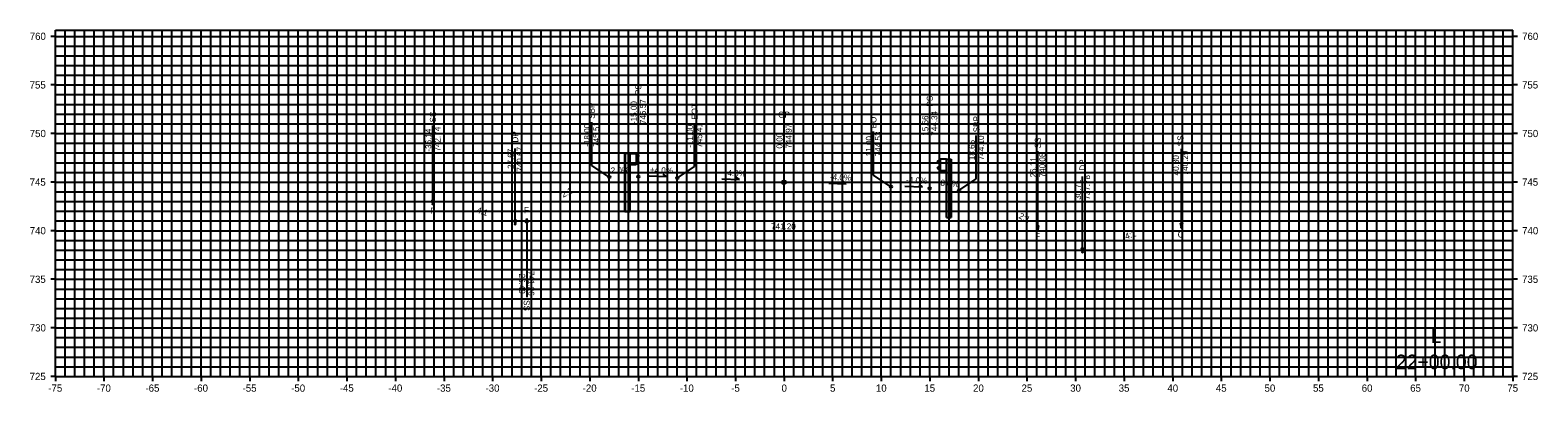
# Model space of a CAD drawing. Extents: x -78 to 78, y 723 to 761.
import ezdxf

# ---------------------------------------------------------------- set-up
doc = ezdxf.new("R2010")
doc.units = 0
for name, color, linetype in [('_CIVIL_CONSTRUCTION', 7, 'Continuous'), ('Default', 7, 'Continuous'), ('E_NCDOT_XS_Center_Line_Elevation_Label', 7, 'Continuous'), ('P_NCDOT_XS_Label_Finished_Grade', 7, 'Continuous'), ('P_NCDOT_XS_Label_Grade_Point', 7, 'Continuous'), ('P_NCDOT_XS_Label_Grading_Side_Slope', 7, 'Continuous'), ('P_NCDOT_XS_Label_Slope_Half_Size', 7, 'Continuous'), ('P_NCDOT_XS_Label_Slope_Superelevation', 7, 'Continuous'), ('P_NCDOT_XS_Leader_Line', 7, 'Continuous'), ('P_NCDOT_XS_Sheet_Alignment_Station_Label', 7, 'Continuous'), ('P_NCDOT_XS_Sheet_Annotation_Label', 7, 'Continuous'), ('P_NCDOT_XS_Sheet_Grid_Border', 7, 'Continuous'), ('P_NCDOT_XS_Slope_Label', 7, 'Continuous'), ('P_RDY_XS_Label_Finished_Grade', 7, 'Continuous'), ('Prop XS Label Slope Superelevation', 7, 'Continuous'), ('Sheet_Grid_Major', 7, 'Continuous'), ('Sheet_Grid_Middle', 7, 'Continuous'), ('Sheet_Grid_Minor', 7, 'Continuous')]:
    doc.layers.add(name, color=color, linetype=linetype)

msp = doc.modelspace()

# ---------------------------------------------------------------- linework, layer by layer
at = {"layer": '_CIVIL_CONSTRUCTION'}
for centre in [(-36.14, 742.74), (-27.67, 740.67), (40.9, 740.32), (30.71, 737.78), (30.71, 737.78)]:
    msp.add_circle(centre, 0.05, dxfattribs=at)
at = {"layer": 'Default'}
for p, q in [((-15.88, 747.95), (-16.38, 747.95)), ((-16.38, 747.95), (-16.36, 747.95)), ((-16.38, 741.95), (-16.38, 747.95)), ((-16.36, 747.95), (-16.36, 741.95)), ((-15.89, 747.95), (-15.88, 747.95)), ((-15.89, 741.95), (-15.89, 747.95)), ((-15.88, 747.95), (-15.21, 747.95)), ((-15.88, 747.95), (-15.88, 741.95)), ((-15.21, 747.95), (-15.21, 746.78)), ((-15.21, 746.78), (-15.88, 746.78)), ((-15.21, 747.87), (-15.12, 747.85)), ((-15.21, 747.41), (-15.21, 747.37)), ((-15.21, 747.37), (-15.21, 747.32)), ((-15.12, 746.88), (-15.21, 746.86)), ((-14.97, 747.62), (-15.18, 747.48)), ((-15.18, 747.25), (-14.97, 747.11)), ((-15.1, 747.85), (-14.97, 747.75)), ((-14.97, 746.98), (-15.1, 746.88)), ((15.94, 747.27), (15.8, 747.17)), ((15.8, 746.4), (15.94, 746.3)), ((15.81, 747.04), (16.01, 746.9)), ((16.01, 746.67), (15.81, 746.53)), ((16.04, 747.29), (15.96, 747.27)), ((16.71, 747.37), (16.05, 747.37)), ((16.05, 747.37), (16.05, 746.2)), ((16.05, 746.83), (16.05, 746.78)), ((16.05, 746.78), (16.05, 746.74)), ((16.71, 747.37), (17.21, 747.37)), ((16.73, 747.37), (16.71, 747.37)), ((16.71, 747.37), (16.71, 741.37)), ((16.73, 741.37), (16.73, 747.37)), ((17.21, 747.37), (17.2, 747.37)), ((17.2, 747.37), (17.2, 741.37)), ((17.21, 741.37), (17.21, 747.37)), ((15.96, 746.3), (16.04, 746.28)), ((16.05, 746.2), (16.71, 746.2)), ((-15.88, 741.95), (-16.38, 741.95)), ((-16.36, 741.95), (-16.38, 741.95)), ((-15.88, 741.95), (-15.89, 741.95)), ((16.71, 741.37), (17.21, 741.37)), ((16.71, 741.37), (16.73, 741.37)), ((17.2, 741.37), (17.21, 741.37))]:
    msp.add_line(p, q, dxfattribs=at)
for centre, radius, start, end in [((-15.13, 747.41), 0.0787, 124.6522, 179.98), ((-15.13, 747.32), 0.0787, 180.02, 235.3478), ((-15.12, 747.82), 0.0328, 54.7024, 80), ((-15.12, 746.91), 0.0328, 280, 305.2976), ((-15.01, 747.69), 0.0787, 304.6522, 54.7024), ((-15.01, 747.05), 0.0787, 305.2976, 55.3478), ((15.85, 747.11), 0.0787, 125.2976, 235.3478), ((15.85, 746.46), 0.0787, 124.6522, 234.7024), ((15.96, 747.24), 0.0328, 100, 125.2976), ((15.97, 746.83), 0.0787, 0.02, 55.3478), ((15.97, 746.74), 0.0787, 304.6522, 359.98), ((15.96, 746.33), 0.0328, 234.7024, 260)]:
    msp.add_arc(centre, radius, start, end, dxfattribs=at)
at = {"layer": 'P_NCDOT_XS_Leader_Line'}
for p, q in [((-15, 745.57), (-15, 753.37)), ((0, 744.97), (0, 751.21)), ((15, 744.37), (15, 752.17)), ((-36.14, 742.74), (-36.14, 750.84)), ((-27.67, 740.67), (-27.67, 748.47)), ((26.11, 740.08), (26.11, 748.18)), ((40.9, 740.32), (40.9, 748.42)), ((30.71, 737.78), (30.71, 745.58)), ((-26.49, 741.26), (-26.49, 733.16))]:
    msp.add_line(p, q, dxfattribs=at)
for points in [[(0.15, 744.82), (-0.15, 744.82), (-0.15, 745.12), (0.15, 745.12)], [(-36.14, 742.74), (-36.23, 743.15), (-36.05, 743.15)], [(-27.67, 740.67), (-27.76, 741.08), (-27.59, 741.08)], [(-26.49, 741.26), (-26.4, 740.85), (-26.58, 740.85)], [(26.11, 740.08), (26.03, 740.49), (26.2, 740.49)], [(40.9, 740.32), (40.81, 740.73), (40.99, 740.73)], [(30.71, 737.78), (30.62, 738.19), (30.8, 738.19)]]:
    msp.add_lwpolyline(points, close=True, dxfattribs=at)
for centre in [(-18, 745.51), (-15, 745.57), (-11, 745.41), (11, 744.53), (15, 744.37), (18, 744.13)]:
    msp.add_circle(centre, 0.12, dxfattribs=at)
at = {"layer": 'P_NCDOT_XS_Sheet_Grid_Border'}
for p, q in [((-75, 760.64), (75, 760.64)), ((-75, 725), (-75, 760.64)), ((75, 725), (75, 760.64)), ((-75, 725), (75, 725))]:
    msp.add_line(p, q, dxfattribs=at)
at = {"layer": 'P_RDY_XS_Label_Finished_Grade'}
for p, q in [((-19.78, 746.7), (-19.78, 751.18)), ((-9.22, 746.6), (-9.22, 751.08)), ((9.22, 745.72), (9.22, 750.2)), ((19.78, 745.32), (19.78, 749.8)), ((-18, 745.51), (-19.78, 746.7)), ((-11, 745.41), (-9.22, 746.6)), ((11, 744.53), (9.22, 745.72)), ((18, 744.13), (19.78, 745.32))]:
    msp.add_line(p, q, dxfattribs=at)
at = {"layer": 'Prop XS Label Slope Superelevation'}
for p, q in [((-13.9, 745.64), (-12.1, 745.57)), ((-12.1, 745.57), (-12.43, 745.82)), ((-6.4, 745.34), (-4.6, 745.27)), ((-4.6, 745.27), (-4.93, 745.52)), ((4.6, 744.9), (6.4, 744.83)), ((6.4, 744.83), (6.07, 745.08)), ((12.43, 744.59), (14.23, 744.52)), ((14.23, 744.52), (13.89, 744.77))]:
    msp.add_line(p, q, dxfattribs=at)
at = {"layer": 'Sheet_Grid_Major'}
for p, q in [((-70, 725), (-70, 760.64)), ((-60, 725), (-60, 760.64)), ((-50, 725), (-50, 760.64)), ((-40, 725), (-40, 760.64)), ((-30, 725), (-30, 760.64)), ((-20, 725), (-20, 760.64)), ((-10, 725), (-10, 760.64)), ((0, 725), (0, 760.64)), ((10, 725), (10, 760.64)), ((20, 725), (20, 760.64)), ((30, 725), (30, 760.64)), ((40, 725), (40, 760.64)), ((50, 725), (50, 760.64)), ((60, 725), (60, 760.64)), ((70, 725), (70, 760.64)), ((-75, 760), (75, 760)), ((-75, 750), (75, 750)), ((-75, 740), (75, 740)), ((-75, 730), (75, 730))]:
    msp.add_line(p, q, dxfattribs=at)
at = {"layer": 'Sheet_Grid_Middle'}
for p, q in [((-70, 725), (-70, 760.64)), ((-65, 725), (-65, 760.64)), ((-60, 725), (-60, 760.64)), ((-55, 725), (-55, 760.64)), ((-50, 725), (-50, 760.64)), ((-45, 725), (-45, 760.64)), ((-40, 725), (-40, 760.64)), ((-35, 725), (-35, 760.64)), ((-30, 725), (-30, 760.64)), ((-25, 725), (-25, 760.64)), ((-20, 725), (-20, 760.64)), ((-15, 725), (-15, 760.64)), ((-10, 725), (-10, 760.64)), ((-5, 725), (-5, 760.64)), ((0, 725), (0, 760.64)), ((5, 725), (5, 760.64)), ((10, 725), (10, 760.64)), ((15, 725), (15, 760.64)), ((20, 725), (20, 760.64)), ((25, 725), (25, 760.64)), ((30, 725), (30, 760.64)), ((35, 725), (35, 760.64)), ((40, 725), (40, 760.64)), ((45, 725), (45, 760.64)), ((50, 725), (50, 760.64)), ((55, 725), (55, 760.64)), ((60, 725), (60, 760.64)), ((65, 725), (65, 760.64)), ((70, 725), (70, 760.64)), ((-75, 760), (-75.48, 760)), ((-75, 760), (75, 760)), ((75.48, 760), (75, 760)), ((-75, 755), (-75.48, 755)), ((-75, 755), (75, 755)), ((75.48, 755), (75, 755)), ((-75, 750), (-75.48, 750)), ((-75, 750), (75, 750)), ((75.48, 750), (75, 750)), ((-75, 745), (-75.48, 745)), ((-75, 745), (75, 745)), ((75.48, 745), (75, 745)), ((-75, 740), (-75.48, 740)), ((-75, 740), (75, 740)), ((75.48, 740), (75, 740)), ((-75, 735), (-75.48, 735)), ((-75, 735), (75, 735)), ((75.48, 735), (75, 735)), ((-75, 730), (-75.48, 730)), ((-75, 730), (75, 730)), ((75.48, 730), (75, 730)), ((-75, 725), (-75.48, 725)), ((-75, 725), (-75, 724.52)), ((-70, 725), (-70, 724.52)), ((-65, 725), (-65, 724.52)), ((-60, 725), (-60, 724.52)), ((-55, 725), (-55, 724.52)), ((-50, 725), (-50, 724.52)), ((-45, 725), (-45, 724.52)), ((-40, 725), (-40, 724.52)), ((-35, 725), (-35, 724.52)), ((-30, 725), (-30, 724.52)), ((-25, 725), (-25, 724.52)), ((-20, 725), (-20, 724.52)), ((-15, 725), (-15, 724.52)), ((-10, 725), (-10, 724.52)), ((-5, 725), (-5, 724.52)), ((0, 725), (0, 724.52)), ((5, 725), (5, 724.52)), ((10, 725), (10, 724.52)), ((15, 725), (15, 724.52)), ((20, 725), (20, 724.52)), ((25, 725), (25, 724.52)), ((30, 725), (30, 724.52)), ((35, 725), (35, 724.52)), ((40, 725), (40, 724.52)), ((45, 725), (45, 724.52)), ((50, 725), (50, 724.52)), ((55, 725), (55, 724.52)), ((60, 725), (60, 724.52)), ((65, 725), (65, 724.52)), ((70, 725), (70, 724.52)), ((75, 725), (75, 724.52)), ((75.48, 725), (75, 725))]:
    msp.add_line(p, q, dxfattribs=at)
at = {"layer": 'Sheet_Grid_Minor'}
for p, q in [((-74, 725), (-74, 760.64)), ((-73, 725), (-73, 760.64)), ((-72, 725), (-72, 760.64)), ((-71, 725), (-71, 760.64)), ((-69, 725), (-69, 760.64)), ((-68, 725), (-68, 760.64)), ((-67, 725), (-67, 760.64)), ((-66, 725), (-66, 760.64)), ((-64, 725), (-64, 760.64)), ((-63, 725), (-63, 760.64)), ((-62, 725), (-62, 760.64)), ((-61, 725), (-61, 760.64)), ((-59, 725), (-59, 760.64)), ((-58, 725), (-58, 760.64)), ((-57, 725), (-57, 760.64)), ((-56, 725), (-56, 760.64)), ((-54, 725), (-54, 760.64)), ((-53, 725), (-53, 760.64)), ((-52, 725), (-52, 760.64)), ((-51, 725), (-51, 760.64)), ((-49, 725), (-49, 760.64)), ((-48, 725), (-48, 760.64)), ((-47, 725), (-47, 760.64)), ((-46, 725), (-46, 760.64)), ((-44, 725), (-44, 760.64)), ((-43, 725), (-43, 760.64)), ((-42, 725), (-42, 760.64)), ((-41, 725), (-41, 760.64)), ((-39, 725), (-39, 760.64)), ((-38, 725), (-38, 760.64)), ((-37, 725), (-37, 760.64)), ((-36, 725), (-36, 760.64)), ((-34, 725), (-34, 760.64)), ((-33, 725), (-33, 760.64)), ((-32, 725), (-32, 760.64)), ((-31, 725), (-31, 760.64)), ((-29, 725), (-29, 760.64)), ((-28, 725), (-28, 760.64)), ((-27, 725), (-27, 760.64)), ((-26, 725), (-26, 760.64)), ((-24, 725), (-24, 760.64)), ((-23, 725), (-23, 760.64)), ((-22, 725), (-22, 760.64)), ((-21, 725), (-21, 760.64)), ((-19, 725), (-19, 760.64)), ((-18, 725), (-18, 760.64)), ((-17, 725), (-17, 760.64)), ((-16, 725), (-16, 760.64)), ((-14, 725), (-14, 760.64)), ((-13, 725), (-13, 760.64)), ((-12, 725), (-12, 760.64)), ((-11, 725), (-11, 760.64)), ((-9, 725), (-9, 760.64)), ((-8, 725), (-8, 760.64)), ((-7, 725), (-7, 760.64)), ((-6, 725), (-6, 760.64)), ((-4, 725), (-4, 760.64)), ((-3, 725), (-3, 760.64)), ((-2, 725), (-2, 760.64)), ((-1, 725), (-1, 760.64)), ((1, 725), (1, 760.64)), ((2, 725), (2, 760.64)), ((3, 725), (3, 760.64)), ((4, 725), (4, 760.64)), ((6, 725), (6, 760.64)), ((7, 725), (7, 760.64)), ((8, 725), (8, 760.64)), ((9, 725), (9, 760.64)), ((11, 725), (11, 760.64)), ((12, 725), (12, 760.64)), ((13, 725), (13, 760.64)), ((14, 725), (14, 760.64)), ((16, 725), (16, 760.64)), ((17, 725), (17, 760.64)), ((18, 725), (18, 760.64)), ((19, 725), (19, 760.64)), ((21, 725), (21, 760.64)), ((22, 725), (22, 760.64)), ((23, 725), (23, 760.64)), ((24, 725), (24, 760.64)), ((26, 725), (26, 760.64)), ((27, 725), (27, 760.64)), ((28, 725), (28, 760.64)), ((29, 725), (29, 760.64)), ((31, 725), (31, 760.64)), ((32, 725), (32, 760.64)), ((33, 725), (33, 760.64)), ((34, 725), (34, 760.64)), ((36, 725), (36, 760.64)), ((37, 725), (37, 760.64)), ((38, 725), (38, 760.64)), ((39, 725), (39, 760.64)), ((41, 725), (41, 760.64)), ((42, 725), (42, 760.64)), ((43, 725), (43, 760.64)), ((44, 725), (44, 760.64)), ((46, 725), (46, 760.64)), ((47, 725), (47, 760.64)), ((48, 725), (48, 760.64)), ((49, 725), (49, 760.64)), ((51, 725), (51, 760.64)), ((52, 725), (52, 760.64)), ((53, 725), (53, 760.64)), ((54, 725), (54, 760.64)), ((56, 725), (56, 760.64)), ((57, 725), (57, 760.64)), ((58, 725), (58, 760.64)), ((59, 725), (59, 760.64)), ((61, 725), (61, 760.64)), ((62, 725), (62, 760.64)), ((63, 725), (63, 760.64)), ((64, 725), (64, 760.64)), ((66, 725), (66, 760.64)), ((67, 725), (67, 760.64)), ((68, 725), (68, 760.64)), ((69, 725), (69, 760.64)), ((71, 725), (71, 760.64)), ((72, 725), (72, 760.64)), ((73, 725), (73, 760.64)), ((74, 725), (74, 760.64)), ((-75, 759), (75, 759)), ((-75, 758), (75, 758)), ((-75, 757), (75, 757)), ((-75, 756), (75, 756)), ((-75, 754), (75, 754)), ((-75, 753), (75, 753)), ((-75, 752), (75, 752)), ((-75, 751), (75, 751)), ((-75, 749), (75, 749)), ((-75, 748), (75, 748)), ((-75, 747), (75, 747)), ((-75, 746), (75, 746)), ((-75, 744), (75, 744)), ((-75, 743), (75, 743)), ((-75, 742), (75, 742)), ((-75, 741), (75, 741)), ((-75, 739), (75, 739)), ((-75, 738), (75, 738)), ((-75, 737), (75, 737)), ((-75, 736), (75, 736)), ((-75, 734), (75, 734)), ((-75, 733), (75, 733)), ((-75, 732), (75, 732)), ((-75, 731), (75, 731)), ((-75, 729), (75, 729)), ((-75, 728), (75, 728)), ((-75, 727), (75, 727)), ((-75, 726), (75, 726))]:
    msp.add_line(p, q, dxfattribs=at)

# ---------------------------------------------------------------- texts
at = {"layer": 'E_NCDOT_XS_Center_Line_Elevation_Label'}
msp.add_text('741.20', height=0.624, dxfattribs=at).set_placement((-1.34, 740.13))
at = {"layer": 'P_NCDOT_XS_Label_Finished_Grade'}
for s, p in [('PS', (-14.69, 753.97)), ('SBP', (-19.49, 751.51)), ('-15.00', (-15.16, 750.97)), ('745.57', (-14.22, 750.97)), ('EOT', (-8.89, 751.41)), ('PS', (15.31, 752.77)), ('745.51', (-19.02, 748.63)), ('EOT', (9.51, 750.53)), ('15.66', (14.84, 749.77)), ('744.34', (15.78, 749.77)), ('SBP', (20.11, 750.13)), ('-18.00', (-19.96, 748.63)), ('-11.00', (-9.36, 748.53)), ('745.41', (-8.42, 748.53)), ('11.00', (9.04, 747.65)), ('744.53', (9.98, 747.65)), ('744.10', (20.58, 747.25)), ('18.66', (19.64, 747.25))]:
    msp.add_text(s, height=0.624, rotation=90, dxfattribs=at).set_placement(p)
at = {"layer": 'P_NCDOT_XS_Label_Grade_Point'}
msp.add_text('GP', height=0.624, dxfattribs=at).set_placement((-0.61, 751.63))
for s, p in [('0.00', (-0.16, 748.45)), ('744.97', (0.78, 748.45))]:
    msp.add_text(s, height=0.624, rotation=90, dxfattribs=at).set_placement(p)
at = {"layer": 'P_NCDOT_XS_Label_Grading_Side_Slope'}
for s, rotation, p in [('SS', 90, (-35.83, 751.14)), ('-36.14', 90, (-36.3, 748.14)), ('742.74', 90, (-35.36, 748.14)), ('SS', 90, (26.43, 748.48)), ('SS', 90, (41.11, 748.69)), ('740.08', 90, (26.89, 745.48)), ('740.29', 90, (41.58, 745.69)), ('26.11', 90, (25.96, 745.48)), ('40.80', 90, (40.64, 745.69)), ('-26.49', 270, (-27.27, 735.86)), ('741.26', 270, (-26.33, 735.86)), ('SS', 270, (-26.8, 732.86))]:
    msp.add_text(s, height=0.624, rotation=rotation, dxfattribs=at).set_placement(p)
for s, p in [('F', (-36.42, 741.75)), ('F', (-26.76, 741.8)), ('F', (25.83, 739.1)), ('C', (40.51, 739.3))]:
    msp.add_text(s, height=0.624, dxfattribs=at).set_placement(p)
at = {"layer": 'P_NCDOT_XS_Label_Slope_Half_Size'}
msp.add_text('-2.0%', height=0.624, rotation=1.1458, dxfattribs=at).set_placement((-18.12, 745.87))
at = {"layer": 'P_NCDOT_XS_Label_Slope_Superelevation'}
for s, p in [('+4.0%', (-6.33, 745.66)), ('-4.0%', (4.71, 745.22))]:
    msp.add_text(s, height=0.624, rotation=357.7094, dxfattribs=at).set_placement(p)
at = {"layer": 'P_NCDOT_XS_Leader_Line'}
for s, rotation, p in [('DP', 90, (-27.36, 749.07)), ('-27.67', 90, (-27.83, 746.07)), ('740.67', 90, (-26.89, 746.07)), ('DP', 90, (31.02, 746.18)), ('30.71', 90, (30.55, 743.18)), ('737.78', 90, (31.49, 743.18)), ('4:1', 341.0488, (-31.7, 741.88)), ('4:1', 18.3029, (35.2, 739.09))]:
    msp.add_text(s, height=0.624, rotation=rotation, dxfattribs=at).set_placement(p)
at = {"layer": 'P_NCDOT_XS_Sheet_Alignment_Station_Label'}
for s, p in [('L', (66.54, 728.45)), ('22+00.00', (62.95, 725.75))]:
    msp.add_text(s, height=1.5, dxfattribs=at).set_placement(p)
at = {"layer": 'P_NCDOT_XS_Sheet_Annotation_Label'}
for s, p in [('760', (-77.64, 759.63)), ('760', (75.96, 759.63)), ('755', (-77.65, 754.63)), ('755', (75.95, 754.63)), ('750', (-77.64, 749.63)), ('750', (75.96, 749.63)), ('745', (-77.65, 744.63)), ('745', (75.95, 744.63)), ('740', (-77.64, 739.63)), ('740', (75.96, 739.63)), ('735', (-77.65, 734.63)), ('735', (75.95, 734.63)), ('730', (-77.64, 729.63)), ('730', (75.96, 729.63)), ('725', (-77.65, 724.63)), ('725', (75.95, 724.63)), ('-75', (-75.73, 723.43)), ('-70', (-70.73, 723.43)), ('-65', (-65.73, 723.43)), ('-60', (-60.73, 723.43)), ('-55', (-55.73, 723.43)), ('-50', (-50.73, 723.43)), ('-45', (-45.73, 723.43)), ('-40', (-40.73, 723.43)), ('-35', (-35.73, 723.43)), ('-30', (-30.73, 723.43)), ('-25', (-25.73, 723.43)), ('-20', (-20.73, 723.43)), ('-15', (-15.73, 723.43)), ('-10', (-10.73, 723.43)), ('-5', (-5.44, 723.43)), ('0', (-0.26, 723.43)), ('5', (4.73, 723.43)), ('10', (9.45, 723.43)), ('15', (14.44, 723.43)), ('20', (19.45, 723.43)), ('25', (24.44, 723.43)), ('30', (29.45, 723.43)), ('35', (34.44, 723.43)), ('40', (39.45, 723.43)), ('45', (44.44, 723.43)), ('50', (49.45, 723.43)), ('55', (54.44, 723.43)), ('60', (59.45, 723.43)), ('65', (64.44, 723.43)), ('70', (69.45, 723.43)), ('75', (74.44, 723.43))]:
    msp.add_text(s, height=0.744, dxfattribs=at).set_placement(p)
at = {"layer": 'P_NCDOT_XS_Slope_Label'}
for s, rotation, p in [('+4.0%', 357.7094, (-13.83, 745.96)), ('-4.0%', 357.7094, (12.54, 744.91)), ('-8.0%', 355.4261, (15.8, 744.66)), ('2:1', 26.5651, (-22.74, 743.39)), ('2:1', 333.4349, (24.09, 741.32))]:
    msp.add_text(s, height=0.624, rotation=rotation, dxfattribs=at).set_placement(p)

doc.saveas('drawing.dxf')
